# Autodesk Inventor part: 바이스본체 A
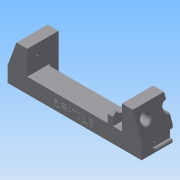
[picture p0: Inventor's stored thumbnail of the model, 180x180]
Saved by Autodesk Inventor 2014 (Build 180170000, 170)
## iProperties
Created: 2017-04
Part Number: 바이스본체 A
Material: 알루미늄 6061
Document SubType Name: Modeling
Designer: mduedu
Density: 2.71 g/cm^3
Appearance: 기본값
Mass: 246.801 g
Surface Area: 212.061 cm^2
Volume: 91.0704 cm^3
Author: mduedu
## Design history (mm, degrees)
sketch "스케치1"
  geometry: L1 (-75, 0)-(75, 0); L2 (-75, 0)-(-75, 17); L3 (-53, 17)-(53, 17); L4 (75, 17)-(75, 0); L5 (-75, 17)-(-65.173, 44); L6 (-65.173, 44)-(-53, 44); L7 (-53, 44)-(-53, 17); L8 (0, 0)-(0, 17); L9 (75, 17)-(65.173, 44); L10 (65.173, 44)-(53, 44); L11 (53, 44)-(53, 17); 1 further point
  constraints: 22 end point, 4 perpendicular, 2 horizontal alignment, 2 midpoint, 2 symmetric about line, 1 coincident, 1 collinear, 1 horizontal, 1 vertical
  dimensions: "d0" = 150 distance of L1.start L1.end; "d1" = 17 distance of L1.start L2.end; "d2" = 27 distance of L3.start L6.end; "d3" = 22 distance of L3.start L2.end; "d4" = 70 deg angle of L3 L5; "d54" = 20 deg angle of L9 L4
extrude "돌출1" new body sketch "스케치1" stored distance "d5" = 70; taper "d6" = 0 deg
sketch "스케치2"
  geometry: L1 (0, 70)-(106, 70) reference; L2 (106, 70)-(106, 0) reference; L3 (106, 0)-(0, 0) reference; L4 (0, 47)-(106, 47); L5 (106, 47)-(106, 23); L6 (106, 23)-(0, 23); L7 (0, 23)-(0, 47); L8 (0, 70)-(0, 0) reference; 2 further points
  constraints: 8 end point, 2 parallel, 2 point on line, 1 horizontal, 1 horizontal alignment, 1 midpoint, 1 perpendicular
  dimensions: "d7" = 24 distance between parallel lines of L6 L4
extrude "돌출2" cut sketch "스케치2" stored distance "d9" = 70; taper "d10" = 0 deg
sketch "스케치3"
  geometry: L1 (22, -23)-(128, -23) reference; L2 (128, -47)-(22, -47) reference; L3 (22, -18)-(128, -18); L4 (128, -52)-(22, -52); L5 (22, -18)-(22, -52); L6 (128, -18)-(128, -52); 1 further point
  constraints: 8 end point, 3 parallel, 2 point on line, 1 perpendicular
  dimensions: "d11" = 5 distance between parallel lines of L3 L1; "d12" = 5 distance between parallel lines of L4 L2
extrude "돌출3" cut sketch "스케치3" distance "d13" = 12; taper "d14" = 0 deg
fillet "모깎기1" dims "d15" = 3, "d16" = 3
sketch "스케치4"
  geometry: L1 (103, 23)-(3, 23) reference; L2 (0, 26)-(0, 0) reference; L3 (106, 0)-(0, 0) reference; L4 (106, 26)-(106, 0) reference; L5 (96, 0)-(90, 0); L6 (90, 0)-(90, 19.5); L7 (96, 19.5)-(96, 0); L8 (90, 19.5)-(96, 19.5); A1 r 3 centre (3, 26) between (0, 26) and (3, 23) reference; A2 r 3 centre (103, 26) between (103, 23) and (106, 26) reference; 1 further point
  constraints: 8 end point, 2 perpendicular, 1 horizontal, 1 parallel, 1 point on line
  dimensions: "d17" = 10 distance between parallel lines of L7 L4; "d18" = 6 distance between parallel lines of L7 L6; "d27" = 3.5 distance between parallel lines of L8 L1
extrude "돌출4" join sketch "스케치4" distance "d19" = 12; taper "d20" = 0 deg
chamfer "모따기1" distance "d21" = 3; stored, may be unused: second distance "d22" = 2, angle "d23" = 45 deg
chamfer "모따기2" distance "d24" = 3; stored, may be unused: second distance "d25" = 2, angle "d26" = 45 deg
sketch "스케치5"
  geometry: L1 (-15.5, 35.8)-(-15.5, -25.8) reference; L2 (19.5, 0)-(0, 0) reference; C1 r 6.5 at (9.5, 15); 1 further point
  constraints: 1 centre point
  dimensions: "d28" = 13 diameter of C1; "d30" = 15 distance from line of C1.centre L2; "d31" = 25 distance from line of C1.centre L1
extrude "돌출5" cut sketch "스케치5" stored distance "d32" = 12; taper "d33" = 0 deg
sketch "스케치6"
  geometry: C1 r 5 at (-10, 15); C2 r 5 at (-60, 15); A1 r 6.5 centre (-10, 15) between (-15.766, 12) and (-4.234, 12) reference; A2 r 6.5 centre (-60, 15) between (-65.766, 12) and (-54.234, 12) reference; 1 further point
  constraints: 2 centre point, 2 coincident
  dimensions: "d34" = 10 diameter of C1; "d35" = 10 diameter of C2 (= d34)
extrude "돌출6" cut sketch "스케치6" stored distance "d36" = 12; taper "d37" = 0 deg
chamfer "모따기3" distance "d38" = 1; stored, may be unused: second distance "d39" = 2, angle "d40" = 45 deg
chamfer "모따기4" distance "d41" = 1; stored, may be unused: second distance "d42" = 2, angle "d43" = 45 deg
sketch "스케치7"
  geometry: L1 (-35, 35.8)-(-35, -25.8) reference; L2 (-70, 0)-(0, 0) reference; C1 r 5 at (-35, 15); 1 further point
  constraints: 1 centre point, 1 point on line
  dimensions: "d44" = 10 diameter of C1; "d45" = 15 distance from line of C1.centre L2
extrude "돌출7" cut sketch "스케치7" stored distance "d46" = 12; taper "d47" = 0 deg
chamfer "모따기5" distance "d48" = 1; stored, may be unused: second distance "d49" = 2, angle "d50" = 45 deg
node "작업축1"
sketch "스케치8"
  geometry: L1 (-105, 32)-(105, 32) reference; L2 (58, 32)-(64, 32); L3 (64, 32)-(64, 40); L4 (64, 40)-(58, 40); L5 (58, 40)-(58, 32); L6 (53, 38)-(53, 26) reference; 1 further point
  constraints: 8 end point, 2 parallel, 1 horizontal, 1 perpendicular, 1 point on line
  dimensions: "d51" = 5 distance from line of L6 L2.start; "d52" = 6 distance of L3.end L4.end; "d53" = 16 diameter of L4 L1
revolve "회전1" sketch "스케치8" stored, may be unused: angle "d55" = 90 deg
fillet "모깎기2"
chamfer "모따기6" distance "d56" = 1; stored, may be unused: second distance "d57" = 2, angle "d58" = 45 deg
sketch "스케치9"
  geometry: L1 (17.5, 3)-(52.5, 3); L2 (52.5, 13)-(17.5, 13); L3 (70, 0)-(0, 0) reference; L4 (17.5, 8)-(52.5, 8); A1 r 5 centre (17.5, 8) between (17.5, 13) and (17.5, 3); A2 r 5 centre (52.5, 8) between (52.5, 3) and (52.5, 13); 3 further points
  constraints: 6 end point, 4 point on circle, 3 tangent, 2 centre point, 2 midpoint, 2 parallel, 1 horizontal, 1 vertical alignment
  dimensions: "d59" = 35 distance of L4.start L4.end; "d61" = 5 radius of A2; "d62" = 8 distance between parallel lines of L3 L4
extrude "돌출8" cut sketch "스케치9" distance "d63" = 3; taper "d64" = 0 deg
chamfer "모따기7" distance "d65" = 1; stored, may be unused: second distance "d66" = 2, angle "d67" = 45 deg
chamfer "모따기8" distance "d68" = 1; stored, may be unused: second distance "d69" = 2, angle "d70" = 45 deg
feature "분할1"
sketch "스케치10"
  geometry: L1 (35, 27)-(0, 27) reference; L2 (0, 0)-(0, 27) reference; 1 further point
  dimensions: "d85" = 11.5 distance from line of point (12, 15.5) L1; "d86" = 12 distance from line of point (12, 15.5) L2
hole "구멍1" sketch "스케치10" at (12, 15.5) diameter "d71" = 3.242; stored, may be unused: countersink angle "d75" = 90 deg, drill point angle "d77" = 120 deg; dims "d72" = 6, "d73" = 4, "d74" = 2, "d76" = 8
sketch "스케치11"
  geometry: A1 r 5 centre (17.5, 8) between (17.5, 13) and (17.5, 3) reference; 1 further point
  constraints: 1 coincident
hole "구멍3" sketch "스케치11" at (17.5, 8) diameter "d78" = 2.459; stored, may be unused: countersink angle "d82" = 90 deg, drill point angle "d84" = 120 deg; dims "d79" = 4.5, "d80" = 4, "d81" = 2, "d83" = 6
sketch "스케치12"
  geometry: L1 (-75, 0)-(75, 0) reference; 3 further points
  constraints: 1 midpoint, 1 vertical alignment, 1 other
  dimensions: "d87" = 8 distance of point (0, 8) point (0, 0)
feature "엠보싱1" sketch "스케치12" dims "d7" = 24, "d88" = 0.5, "d89" = 0
node "솔리드1"
mirror "대칭1"
mirror "대칭2"
mirror "대칭3"
mirror "대칭4"
node "투영된 루프1"
